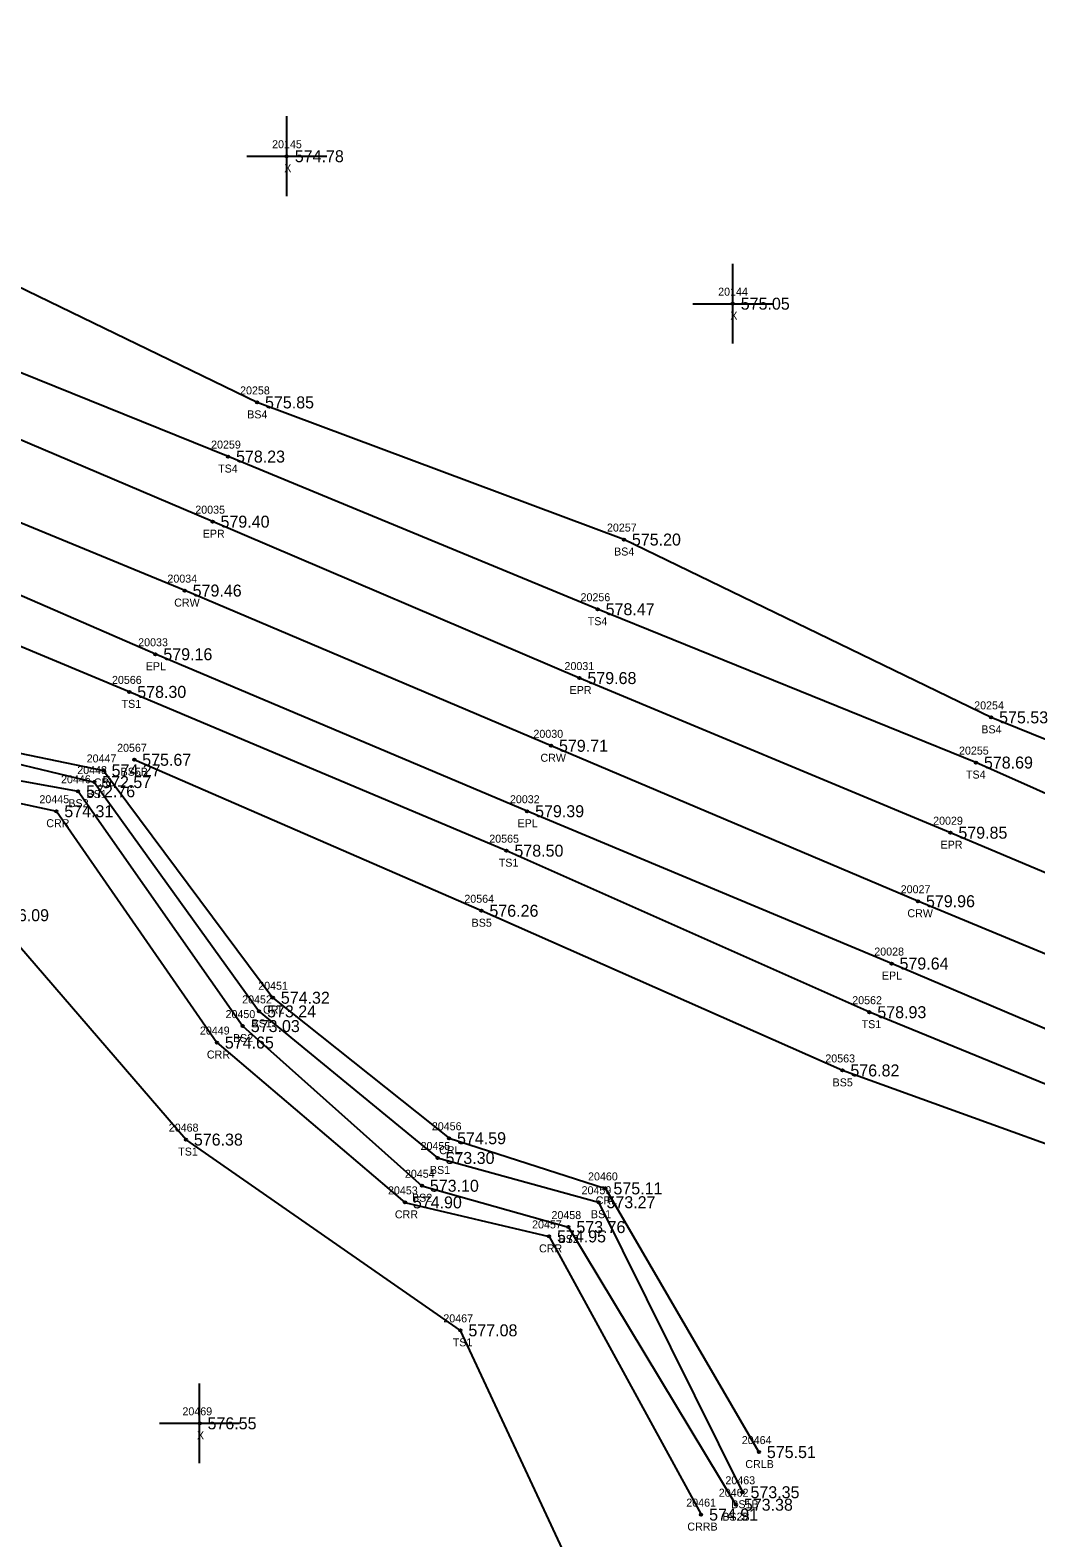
# Model space of a CAD drawing. Extents: x 1664837 to 1666270, y 987403 to 988245.
# Drawn here: x 1665633.6 to 1665759.5, y 987584.2 to 987773 of the extents above; entities that cross this region are included whole.
import ezdxf

# ---------------------------------------------------------------- set-up
doc = ezdxf.new("R2010")
doc.units = 0
for name, color, linetype in [('RD_DTM_BkLn1', 7, 'Continuous'), ('RD_DTM_BkLn2', 7, 'Continuous'), ('RD_DTM_BkLn_txCode', 7, 'Continuous'), ('RD_EX_H2O', 7, 'Continuous'), ('RD_EX_H2O_txCode', 7, 'Continuous'), ('RD_EX_Misc', 7, 'Continuous'), ('RD_EX_Misc_txCode', 7, 'Continuous'), ('RD_EX_Road', 7, 'Continuous'), ('RD_EX_Road_txCode', 7, 'Continuous'), ('RD_EX_TX_H2O_ELEV', 7, 'Continuous'), ('RD_EX_TX_Misc_ELEV', 7, 'Continuous'), ('RD_EX_TX_Road_ELEV', 7, 'Continuous'), ('RD_HC_Survey_ELEV', 7, 'Continuous'), ('RD_HC_Survey_txCode', 7, 'Continuous'), ('RD_SMD_Locator', 7, 'Continuous')]:
    doc.layers.add(name, color=color, linetype=linetype)

msp = doc.modelspace()

# ---------------------------------------------------------------- linework, layer by layer
at = {"layer": 'RD_DTM_BkLn1'}
msp.add_lwpolyline([(1666158.65, 987488.74), (1666112.69, 987508.17), (1666066.71, 987527.94), (1666020.54, 987547.08), (1665974.85, 987566.77), (1665928.96, 987586.52), (1665882.66, 987605.79), (1665836.76, 987625.38), (1665790.86, 987644.81), (1665744.75, 987663.93), (1665698.8, 987683.39), (1665652.93, 987702.82), (1665606.7, 987721.88), (1665561.04, 987742.04), (1665527.67, 987755.89)], dxfattribs=at)
at = {"layer": 'RD_DTM_BkLn2'}
for points in [[(1665937.25, 987616.34), (1665889.99, 987630.17), (1665844.42, 987647.08), (1665801.11, 987667.84), (1665753.91, 987686.95), (1665707.93, 987709.21), (1665661.99, 987726.38), (1665615.37, 987748.93), (1665567.93, 987769.01), (1665555.48, 987787.59)], [(1665521.8, 987775.03), (1665513.35, 987762.3), (1665512.93, 987744.69), (1665504.21, 987730.32), (1665472.11, 987703.59), (1665484.52, 987698.45), (1665513.21, 987703.54), (1665525.98, 987684.44), (1665562.43, 987664.02), (1665594.02, 987677.42), (1665619.36, 987684.18), (1665641.6, 987678.85), (1665662.25, 987650.14), (1665684.59, 987631.79), (1665704.75, 987626.25), (1665722.78, 987589.94)], [(1665936.46, 987601.23), (1665888.67, 987621.23), (1665842.7, 987640.33), (1665797.93, 987660.83), (1665752.01, 987681.29), (1665704.64, 987700.49), (1665658.36, 987719.6), (1665612.75, 987738.02), (1665564.88, 987757.28), (1665542.58, 987772.17), (1665532.86, 987767.81)], [(1666152.82, 987476.83), (1666108.53, 987496.54), (1666062.68, 987516.61), (1666015.91, 987535.8), (1665969.55, 987555.16), (1665926.09, 987572.12), (1665875.73, 987592.3), (1665829.7, 987613.88), (1665783.86, 987631.56), (1665738.66, 987650.04), (1665693.22, 987670.26), (1665645.99, 987690.14), (1665601.24, 987708.82), (1665555.03, 987727.9), (1665522.94, 987740.22)], [(1666117.29, 987404.85), (1666064.63, 987440.28), (1666022.87, 987464.18), (1665976.62, 987505.49), (1665934.85, 987514.58), (1665901.43, 987514.29), (1665891.04, 987542.26), (1665910.76, 987561.83), (1665873.03, 987584.83), (1665826.13, 987605.22), (1665781.49, 987626.06), (1665735.29, 987642.75), (1665690.09, 987662.74), (1665646.61, 987681.64)], [(1665564.17, 987660.42), (1665595.26, 987674.1), (1665619.21, 987681.4), (1665639.59, 987677.7), (1665660.21, 987648.3), (1665682.63, 987628.31), (1665700.98, 987623.14), (1665721.95, 987588.38)], [(1665702.85, 987577.16), (1665687.46, 987610.21), (1665653.08, 987634.09), (1665628.81, 987662.18), (1665596.29, 987663.62), (1665606.22, 987654.81), (1665609.28, 987637.14), (1665625.32, 987619.52)]]:
    msp.add_lwpolyline(points, dxfattribs=at)
at = {"layer": 'RD_EX_H2O'}
for points in [[(1665524.71, 987748.93), (1665523.69, 987745.83), (1665522.12, 987740.87), (1665518.2, 987735.79), (1665482.82, 987708), (1665483.87, 987700.87), (1665513.49, 987706.09), (1665528.04, 987685.52), (1665561.97, 987665.98), (1665593.48, 987679.22), (1665619.37, 987685.12), (1665642.78, 987680.31), (1665663.97, 987651.85), (1665686.03, 987634.26), (1665705.62, 987627.98), (1665724.83, 987594.97)], [(1665567.27, 987659), (1665585.72, 987665.81), (1665597.03, 987673.28), (1665619.21, 987679.02), (1665636.86, 987675.2), (1665656.96, 987646.24), (1665680.5, 987626.23), (1665698.55, 987621.97), (1665717.6, 987587.14)]]:
    msp.add_lwpolyline(points, dxfattribs=at)
at = {"layer": 'RD_EX_Misc'}
for p, q in [((1665665.72, 987752.2), (1665665.72, 987762.2)), ((1665660.72, 987757.2), (1665670.72, 987757.2)), ((1665721.56, 987733.74), (1665721.56, 987743.74)), ((1665716.56, 987738.74), (1665726.56, 987738.74)), ((1665654.79, 987593.57), (1665654.79, 987603.57)), ((1665649.79, 987598.57), (1665659.79, 987598.57))]:
    msp.add_line(p, q, dxfattribs=at)
at = {"layer": 'RD_EX_Road'}
for points in [[(1666163.18, 987497.62), (1666116.6, 987517.39), (1666070.7, 987536.94), (1666024.42, 987556.43), (1665979.02, 987575.67), (1665932.35, 987595.55), (1665886.93, 987614.54), (1665839.87, 987634.25), (1665794.5, 987653.27), (1665748.81, 987672.51), (1665702.36, 987691.87), (1665656.42, 987711.45), (1665610.33, 987731.03), (1665564.85, 987750.93), (1665531.47, 987764.82)], [(1666156.67, 987480.61), (1666109.28, 987500.74), (1666063.55, 987520.04), (1666017.04, 987539.82), (1665971.11, 987559.14), (1665924.88, 987578.79), (1665879.5, 987597.89), (1665833.22, 987617.38), (1665786.91, 987636.81), (1665741.44, 987656.13), (1665695.81, 987675.2), (1665649.26, 987694.85), (1665603.56, 987714.71), (1665558.4, 987733.87), (1665524.71, 987748.93)]]:
    msp.add_lwpolyline(points, dxfattribs=at)
at = {"layer": 'RD_SMD_Locator'}
for centre in [(1665665.72, 987757.2), (1665721.56, 987738.74), (1665661.99, 987726.38), (1665658.36, 987719.6), (1665656.42, 987711.45), (1665707.93, 987709.21), (1665652.93, 987702.82), (1665704.64, 987700.49), (1665649.26, 987694.85), (1665702.36, 987691.87), (1665645.99, 987690.14), (1665753.91, 987686.95), (1665698.8, 987683.39), (1665646.61, 987681.64), (1665642.78, 987680.31), (1665752.01, 987681.29), (1665639.59, 987677.7), (1665641.6, 987678.85), (1665636.86, 987675.2), (1665695.81, 987675.2), (1665748.81, 987672.51), (1665693.22, 987670.26), (1665690.09, 987662.74), (1665744.75, 987663.93), (1665741.44, 987656.13), (1665663.97, 987651.85), (1665662.25, 987650.14), (1665738.66, 987650.04), (1665660.21, 987648.3), (1665656.96, 987646.24), (1665735.29, 987642.75), (1665653.08, 987634.09), (1665686.03, 987634.26), (1665684.59, 987631.79), (1665682.63, 987628.31), (1665705.62, 987627.98), (1665680.5, 987626.23), (1665704.75, 987626.25), (1665700.98, 987623.14), (1665698.55, 987621.97), (1665687.46, 987610.21), (1665654.79, 987598.57), (1665724.83, 987594.97), (1665722.78, 987589.94), (1665717.6, 987587.14), (1665721.95, 987588.38)]:
    msp.add_circle(centre, 0.15, dxfattribs=at)

# ---------------------------------------------------------------- texts
at = {"layer": 'RD_DTM_BkLn_txCode'}
for s, p in [('20258', (1665659.87, 987727.38)), ('BS4', (1665660.76, 987724.38)), ('20259', (1665656.24, 987720.6)), ('TS4', (1665657.12, 987717.6)), ('20257', (1665705.81, 987710.21)), ('BS4', (1665706.7, 987707.21)), ('20256', (1665702.5, 987701.49)), ('TS4', (1665703.4, 987698.49)), ('20566', (1665643.83, 987691.14)), ('TS1', (1665645.03, 987688.14)), ('20254', (1665751.79, 987687.95)), ('BS4', (1665752.68, 987684.95)), ('20567', (1665644.47, 987682.64)), ('20255', (1665749.89, 987682.29)), ('20448', (1665639.48, 987679.85)), ('BS5B', (1665644.91, 987679.64)), ('TS4', (1665750.76, 987679.29)), ('20446', (1665637.45, 987678.7)), ('BS1', (1665640.65, 987676.85)), ('BS2', (1665638.37, 987675.7)), ('20565', (1665691.07, 987671.26)), ('TS1', (1665692.26, 987668.26)), ('20564', (1665687.95, 987663.74)), ('BS5', (1665688.86, 987660.74)), ('20452', (1665660.13, 987651.14)), ('20562', (1665736.52, 987651.04)), ('20450', (1665658.05, 987649.3)), ('BS1', (1665661.3, 987648.14)), ('TS1', (1665737.7, 987648.04)), ('BS2', (1665658.98, 987646.3)), ('20563', (1665733.15, 987643.75)), ('BS5', (1665734.06, 987640.75)), ('20468', (1665650.94, 987635.09)), ('TS1', (1665652.12, 987632.09)), ('20455', (1665682.47, 987632.79)), ('BS1', (1665683.64, 987629.79)), ('20454', (1665680.51, 987629.31)), ('BS2', (1665681.4, 987626.31)), ('20459', (1665702.63, 987627.25)), ('20458', (1665698.86, 987624.14)), ('BS1', (1665703.8, 987624.25)), ('BS2', (1665699.75, 987621.14)), ('20467', (1665685.32, 987611.21)), ('TS1', (1665686.5, 987608.21)), ('20463', (1665720.64, 987590.94)), ('20462', (1665719.81, 987589.38)), ('BS2B', (1665720.25, 987586.38)), ('BS1B', (1665721.37, 987587.94))]:
    msp.add_text(s, height=1, dxfattribs=at).set_placement(p)
at = {"layer": 'RD_EX_H2O_txCode'}
for s, p in [('20447', (1665640.66, 987681.31)), ('CRL', (1665641.55, 987678.31)), ('20445', (1665634.74, 987676.2)), ('CRR', (1665635.6, 987673.2)), ('20451', (1665662.14, 987652.85)), ('CRL', (1665662.74, 987649.85)), ('20449', (1665654.84, 987647.24)), ('CRR', (1665655.71, 987644.24)), ('20456', (1665683.88, 987635.26)), ('CRL', (1665684.8, 987632.26)), ('20460', (1665703.44, 987628.98)), ('20453', (1665678.39, 987627.23)), ('CRL', (1665704.4, 987625.98)), ('CRR', (1665679.25, 987624.23)), ('20457', (1665696.43, 987622.97)), ('CRR', (1665697.3, 987619.97)), ('20464', (1665722.69, 987595.97)), ('CRLB', (1665723.13, 987592.97)), ('20461', (1665715.74, 987588.14)), ('CRRB', (1665715.87, 987585.14))]:
    msp.add_text(s, height=1, dxfattribs=at).set_placement(p)
at = {"layer": 'RD_EX_Misc_txCode'}
for s, p in [('20145', (1665663.88, 987758.2)), ('X', (1665665.4, 987755.2)), ('20144', (1665719.73, 987739.74)), ('X', (1665721.25, 987736.74)), ('20469', (1665652.65, 987599.57)), ('X', (1665654.47, 987596.57))]:
    msp.add_text(s, height=1, dxfattribs=at).set_placement(p)
at = {"layer": 'RD_EX_Road_txCode'}
for s, p in [('20035', (1665654.26, 987712.45)), ('EPR', (1665655.19, 987709.45)), ('20033', (1665647.11, 987695.85)), ('EPL', (1665648.06, 987692.85)), ('20031', (1665700.49, 987692.87)), ('EPR', (1665701.13, 987689.87)), ('20032', (1665693.66, 987676.2)), ('EPL', (1665694.61, 987673.2)), ('20029', (1665746.65, 987673.51)), ('EPR', (1665747.58, 987670.51)), ('20028', (1665739.28, 987657.13)), ('EPL', (1665740.23, 987654.13))]:
    msp.add_text(s, height=1, dxfattribs=at).set_placement(p)
at = {"layer": 'RD_EX_TX_H2O_ELEV'}
for s, p in [('574.27', (1665643.78, 987679.56)), ('574.31', (1665637.86, 987674.45)), ('574.32', (1665664.97, 987651.1)), ('574.65', (1665657.96, 987645.49)), ('574.59', (1665687.03, 987633.51)), ('574.90', (1665681.5, 987625.48)), ('575.11', (1665706.62, 987627.23)), ('574.95', (1665699.55, 987621.22)), ('575.51', (1665725.83, 987594.22)), ('574.91', (1665718.6, 987586.39))]:
    msp.add_text(s, height=1.5, dxfattribs=at).set_placement(p)
at = {"layer": 'RD_EX_TX_Misc_ELEV'}
for s, p in [('574.78', (1665666.72, 987756.45)), ('575.05', (1665722.56, 987737.99)), ('575.85', (1665662.99, 987725.63)), ('578.23', (1665659.36, 987718.85)), ('575.20', (1665708.93, 987708.46)), ('578.47', (1665705.64, 987699.74)), ('578.30', (1665646.99, 987689.39)), ('575.53', (1665754.91, 987686.2)), ('575.67', (1665647.61, 987680.89)), ('578.69', (1665753.01, 987680.54)), ('572.76', (1665640.59, 987676.95)), ('572.57', (1665642.6, 987678.1)), ('578.50', (1665694.22, 987669.51)), ('576.09', (1665629.81, 987661.43)), ('576.26', (1665691.09, 987661.99)), ('573.24', (1665663.25, 987649.39)), ('578.93', (1665739.66, 987649.29)), ('573.03', (1665661.21, 987647.55)), ('576.82', (1665736.29, 987642)), ('576.38', (1665654.08, 987633.34)), ('573.30', (1665685.59, 987631.04)), ('573.10', (1665683.63, 987627.56)), ('573.27', (1665705.75, 987625.5)), ('573.76', (1665701.98, 987622.39)), ('577.08', (1665688.46, 987609.46)), ('576.55', (1665655.79, 987597.82)), ('573.38', (1665722.95, 987587.63)), ('573.35', (1665723.78, 987589.19))]:
    msp.add_text(s, height=1.5, dxfattribs=at).set_placement(p)
at = {"layer": 'RD_EX_TX_Road_ELEV'}
for s, p in [('579.40', (1665657.42, 987710.7)), ('579.16', (1665650.26, 987694.1)), ('579.68', (1665703.36, 987691.12)), ('579.39', (1665696.81, 987674.45)), ('579.85', (1665749.81, 987671.76)), ('579.64', (1665742.44, 987655.38))]:
    msp.add_text(s, height=1.5, dxfattribs=at).set_placement(p)
at = {"layer": 'RD_HC_Survey_ELEV'}
for s, p in [('579.46', (1665653.93, 987702.07)), ('579.71', (1665699.8, 987682.64)), ('579.96', (1665745.75, 987663.18))]:
    msp.add_text(s, height=1.5, dxfattribs=at).set_placement(p)
at = {"layer": 'RD_HC_Survey_txCode'}
for s, p in [('20034', (1665650.77, 987703.82)), ('CRW', (1665651.62, 987700.82)), ('20030', (1665696.6, 987684.39)), ('CRW', (1665697.48, 987681.39)), ('20027', (1665742.59, 987664.93)), ('CRW', (1665743.43, 987661.93))]:
    msp.add_text(s, height=1, dxfattribs=at).set_placement(p)

doc.saveas('drawing.dxf')
